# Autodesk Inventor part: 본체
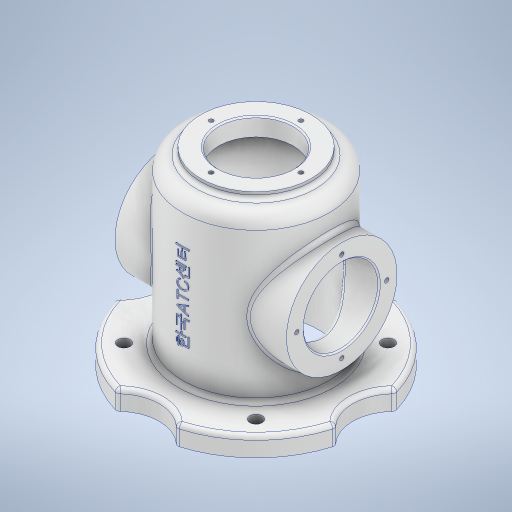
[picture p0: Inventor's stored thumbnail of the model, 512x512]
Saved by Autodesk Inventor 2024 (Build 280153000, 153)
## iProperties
Created: 2026-07
Part Number: 본체
Material: 알루미늄 6061
Document SubType Name: Modeling
Designer: com
Density: 2.7 g/cm^3
Appearance: 알루미늄 - 평지
Author: com
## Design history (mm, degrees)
sketch "스케치1"
  geometry: L1 (0, 0)-(0, 137); L2 (40, 137)-(40, 132); L3 (40, 132)-(53, 132); L4 (53, 132)-(53, 0); L5 (53, 0)-(0, 0); L6 (40, 137)-(0, 137); L7 (0, 0)-(82, 0); L8 (82, 0)-(82, 14); L9 (82, 14)-(0, 14); L10 (0, 14)-(0, 0); 2 further points
  constraints: 20 end point, 5 perpendicular, 2 parallel, 1 horizontal, 1 vertical
  dimensions: "d0" = 137 distance of L1.start L1.end; "d1" = 5 distance of L2.start L2.end; "d2" = 80 diameter of L2 L1; "d3" = 106 diameter of L4 L1; "d4" = 164 diameter of L8 L1; "d5" = 14 distance between parallel lines of L5 L9
revolve "회전1" sketch "스케치1" stored, may be unused: angle "d6" = 90 deg
sketch "스케치2" dims "d22" = 0
  geometry: L1 (-62, 68)-(62, 68); L2 (0, 0)-(0, 143); L3 (82, 0)-(-82, 0) reference; L4 (-62, 68)-(-62, 108); L5 (-62, 108)-(62, 108); L6 (62, 108)-(62, 68); 2 further points
  constraints: 10 end point, 2 midpoint, 2 perpendicular, 2 vertical, 1 horizontal, 1 vertical alignment
  dimensions: "d7" = 68 distance between parallel lines of L3 L1; "d8" = 124 distance of L1.start L1.end; "d9" = 80 diameter of L5 L1
revolve "회전2" sketch "스케치2" stored, may be unused: angle "d10" = 90 deg
sketch "스케치3"
  geometry: L1 (0, 0)-(0, 171.391); L2 (82, 0)-(-82, 0) reference; L3 (-45, 0)-(-45, 121); L4 (-42, 124)-(0, 124); L5 (0, 124)-(-27, 124); L6 (-27, 124)-(-27, 137); L7 (-27, 137)-(0, 137); L8 (0, 137)-(0, 124); L9 (40, 137)-(-40, 137) reference; A1 r 3 centre (-42, 121) between (-42, 124) and (-45, 121); 4 further points
  constraints: 14 end point, 4 point on line, 2 midpoint, 2 parallel, 2 perpendicular, 2 point on circle, 2 tangent, 2 vertical, 1 centre point, 1 horizontal
  dimensions: "d11" = 54 diameter of point (-27, 130.5) L1; "d12" = 90 diameter of L3 L1; "d13" = 124 distance of L3.start point (-45, 124); "d14" = 3 radius of A1
revolve "회전3" sketch "스케치3" stored, may be unused: angle "d15" = 90 deg
sketch "스케치4"
  geometry: C1 r 40 at (0, 0) reference; C2 r 27 at (0, 0); 1 further point
  constraints: 1 centre point, 1 coincident
  dimensions: "d16" = 54 diameter of C2
extrude "돌출1" cut sketch "스케치4" extent not by distance; stored distance "d17" = 0; taper "d18" = 0 deg
fillet "모깎기1" dims "d19" = 3
sketch "스케치5"
  geometry: C1 r 30 at (-100, 0); 1 further point
  constraints: 1 centre point, 1 horizontal alignment
  dimensions: "d20" = 60 diameter of C1; "d21" = 100 distance of point (0, 0) C1.centre
extrude "돌출2" cut sketch "스케치5" extent not by distance; stored distance "d22" = 0; taper "d23" = 0 deg
sketch "스케치6"
  geometry: L1 (100, 0)-(100, 67.5); L2 (100, 0)-(52.27, 47.73); C1 r 4.5 at (52.27, 47.73); C2 r 4.5 at (52.27, -47.73); C3 r 4.5 at (147.73, -47.73); C4 r 4.5 at (147.73, 47.73); A1 r 67.5 centre (100, 0) between (52.27, 47.73) and (100, 67.5); 1 further point
  constraints: 5 centre point, 4 end point, 2 coincident, 2 point on circle, 1 vertical, 9 other
  dimensions: "d27" = 135 diameter of A1; "d28" = 45 deg angle of L1 L2; "d29" = 9 diameter of C1; "d32" = 360 deg dimension on point (100, 0) C1.centre (derived)
extrude "돌출3" cut sketch "스케치6" extent not by distance; stored distance "d34" = 0; taper "d35" = 0 deg
sketch "스케치7" dims "d36" = 65
  geometry: C1 r 27 at (0, 0) reference; 6 further points
  constraints: 2 vertical alignment, 1 coincident, 7 other
  dimensions: "d39" = 360 deg dimension on point (0, 0) point (0, 32.5) (derived)
hole "구멍1" sketch "스케치7" at (0, 32.5), (-32.5, 0), (0, -32.5), (32.5, 0) diameter "d41" = 3.242; stored, may be unused: countersink angle "d45" = 90 deg, drill point angle "d47" = 118 deg; dims "d42" = 8, "d43" = 10, "d44" = 5.7, "d46" = 10
sketch "스케치8" dims "d48" = 65
  geometry: C1 r 27 at (0, 0) reference; 6 further points
  constraints: 1 coincident, 1 vertical alignment, 7 other
  dimensions: "d51" = 360 deg dimension on point (0, 0) point (0, 32.5) (derived)
hole "구멍2" sketch "스케치8" at (0, 32.5), (-32.5, 0), (0, -32.5), (32.5, 0) diameter "d53" = 3.242; stored, may be unused: countersink angle "d57" = 90 deg, drill point angle "d59" = 118 deg; dims "d54" = 8, "d55" = 4, "d56" = 2, "d58" = 10
chamfer "모따기1" distance "d60" = 1; stored, may be unused: second distance "d61" = 2, angle "d62" = 45 deg
fillet "모깎기2" dims "d63" = 3
fillet "모깎기3" dims "d64" = 10
sketch "스케치9"
  geometry: L1 (45, 0)-(-45, 0) reference; 3 further points
  constraints: 1 midpoint, 1 vertical alignment, 1 other
  dimensions: "d65" = 70 distance from line of point (0, 70) L1
feature "엠보싱1" sketch "스케치9" dims "d0" = 137, "d1" = 5, "d2" = 80, "d3" = 106, "d4" = 164, "d5" = 14, "d66" = 0.5, "d67" = 0
fillet "모깎기4" dims "d68" = 3
node "솔리드1"
pattern_circular "원형 패턴1" dims angle "d25" = 360 deg
mirror "미러1"
feature "A9D066F2-1C7D-4E18-AEED-F7BC21143FA4" dims "d41" = 3.242, "d42" = 8, "d43" = 10, "d44" = 5.7, "d45" = 90 deg, "d46" = 10, "d47" = 118 deg
